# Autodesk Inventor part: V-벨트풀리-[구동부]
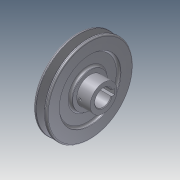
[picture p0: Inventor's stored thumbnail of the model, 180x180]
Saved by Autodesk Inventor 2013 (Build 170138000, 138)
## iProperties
Company: 한국ATC센터
Created: 2014-10
Part Number: V-벨트풀리-[구동부]
Document SubType Name: Modeling
Designer: 한국ATC센터
Density: 7.86 g/cm^3
Material: 강, 연강
Mass: 1515.01 g
Surface Area: 468.125 cm^2
Volume: 192.75 cm^3
Author: KYOUNG IL JANG
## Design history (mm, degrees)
sketch "스케치1"
  geometry: L1 (-20, 0)-(20, 0); L2 (-20, 0)-(-20, 26); L3 (-20, 26)-(-16, 26); L4 (-16, 26)-(-16, 46); L5 (-16, 46)-(-20, 46); L6 (-20, 46)-(-20, 64.5); L7 (-20, 64.5)-(-16.062, 64.5); L8 (-16.062, 64.5)-(-12.001, 52); L9 (-12.001, 52)-(-7.999, 52); L10 (-7.999, 52)-(-3.938, 64.5); L11 (-3.938, 64.5)-(0, 64.5); L12 (0, 64.5)-(0, 46); L13 (0, 46)-(-4, 46); L14 (-4, 46)-(-4, 26); L15 (-4, 26)-(0, 26); L16 (0, 26)-(0, 20); L17 (0, 20)-(20, 20); L18 (20, 20)-(20, 0); L19 (-14.6, 60)-(-5.4, 60); 2 further points
  constraints: 38 end point, 11 parallel, 7 collinear, 3 equal length, 3 perpendicular, 2 point on line, 1 coincident, 1 horizontal, 1 midpoint
  dimensions: "d0" = 40 distance of L1.start L1.end; "d1" = 4.5 distance between parallel lines of L7 L19; "d2" = 8 distance between parallel lines of L9 L19; "d3" = 9.2 distance of L19.start L19.end; "d4" = 36 deg angle of L10 L8; "d5" = 20 distance between parallel lines of L12 L6; "d6" = 120 diameter of L19 L1; "d7" = 4 distance of L2.end L3.end; "d8" = 52 diameter of L3 L1; "d9" = 92 diameter of L5 L1; "d10" = 40 diameter of L17 L1
revolve "회전1" sketch "스케치1" stored, may be unused: angle "d11" = 90 deg
sketch "스케치2"
  geometry: L1 (-4, 11.843)-(-4, 16.5); L2 (-4, 16.5)-(4, 16.5); L3 (4, 16.5)-(4, 11.843); A1 r 12.5 centre (0, 0) between (-4, 11.843) and (4, 11.843); 1 further point
  constraints: 6 end point, 2 parallel, 2 point on circle, 1 centre point, 1 coincident, 1 horizontal, 1 vertical
  dimensions: "d12" = 25 diameter of A1; "d13" = 8 distance of L1.end L2.end; "d14" = 29 dimension on A1 L2
extrude "돌출1" cut sketch "스케치2" stored distance "d15" = 10; taper "d16" = 0 deg
chamfer "모따기1" distance "d17" = 1; stored, may be unused: second distance "d18" = 2, angle "d19" = 45 deg
node "작업 평면1"
sketch "스케치3"
  geometry: L1 (10, -20)-(10, 20) reference; 3 further points
  constraints: 1 horizontal alignment, 1 midpoint
  dimensions: "d20" = 15 distance from line of L1 point (-5, 0)
hole "구멍1" sketch "스케치3" at (-5, 0) diameter "d21" = 4.459; stored, may be unused: countersink angle "d25" = 90 deg, drill point angle "d27" = 118 deg; dims "d22" = 6, "d23" = 4, "d24" = 2, "d26" = 8
fillet "모깎기1" dims "d28" = 3, "d29" = 2, "d30" = 0.5, "d31" = 1
node "솔리드1"
